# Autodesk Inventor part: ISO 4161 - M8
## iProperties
Created: 2001-08
Part Number: ISO 4161 - M8
Catalog Web Link: file:///D:/Program%20Files/Autodesk/Inventor%205/Content/Iso/index.htm?doNavigateId=73EBC748-060C-4D45-9290-9CDEDB95591D|463F0C0B51F7492583066CCB99A98EC1|true
Description: Hex Nut with Flange
Document SubType Name: Standard Catalog Part
Standard: ISO 4161 - M8
Designer: Martin Budgell
Control State: 0
Master: False
Checked Out: False
Length Units: 11269
Angle Units: 11279
Time Units: 11290
Mass Units: 11283
Shininess: 3
Angle Display Precision: 2
Document Length Units: 11269
Document Angle Units: 11279
Document Time Units: 11290
Document Mass Units: 11283
Document Length Units Precision: 3
Document Angle Units Precision: 2
Compacted: True
CLASSIFICATION: 31161727 un/spsc
MANUFACTURER: ISO Standard System
Density: 0.0
Volumn: 0.0
Area: 0.0
PropertySet Name: Model Information
Author: Martin Budgell
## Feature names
1. Base1
